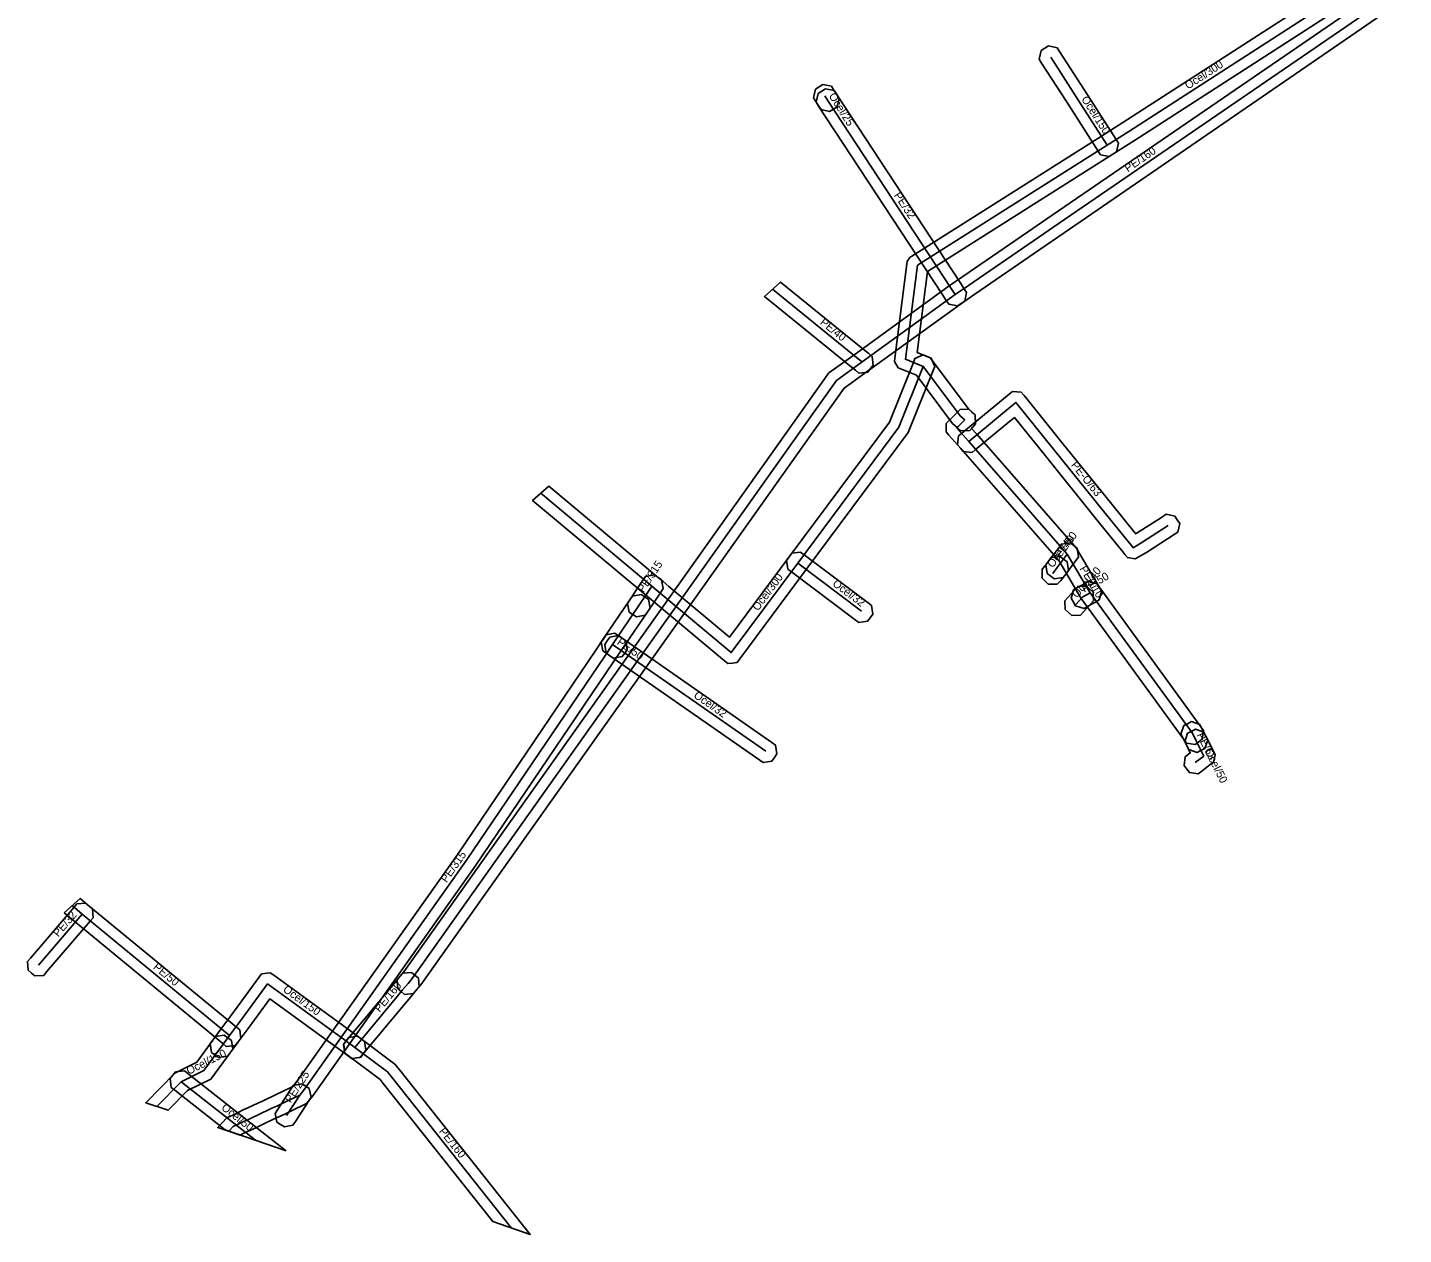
# Model space of a CAD drawing. Extents: x -492768 to -492424, y -1126490 to -1126252.
# Drawn here: x -492768.3 to -492639.3, y -1126489.8 to -1126376.7 of the extents above; entities that cross this region are included whole.
import ezdxf

# ---------------------------------------------------------------- set-up
doc = ezdxf.new("R2010")
doc.units = 0
for name, color, linetype in [('1', 7, 'Continuous'), ('14', 7, 'Continuous'), ('20', 7, 'Continuous'), ('24', 7, 'Continuous'), ('30', 7, 'Continuous')]:
    doc.layers.add(name, color=color, linetype=linetype)

msp = doc.modelspace()

# ---------------------------------------------------------------- linework, layer by layer
at = {"layer": '1'}
for points in [[(-492618.9, -1126357.81), (-492664.52, -1126387.26), (-492666.55, -1126388.54), (-492683.91, -1126399.53), (-492684.9, -1126407.12), (-492683.68, -1126407.61), (-492680.08, -1126412.41), (-492679.76, -1126412.7), (-492679.45, -1126412.97), (-492679.41, -1126413.8), (-492679.68, -1126414.11), (-492679.96, -1126414.42), (-492680.79, -1126414.46), (-492681.1, -1126414.18), (-492681.56, -1126413.77), (-492684.95, -1126409.26), (-492686.36, -1126408.69), (-492686.68, -1126408.56), (-492687.02, -1126407.97), (-492686.98, -1126407.64), (-492685.84, -1126398.81), (-492685.81, -1126398.59), (-492685.57, -1126398.21), (-492685.38, -1126398.09), (-492667.62, -1126386.85), (-492665.59, -1126385.57), (-492619.98, -1126356.13)], [(-492640.16, -1126374.66), (-492671.11, -1126395.9), (-492673.4, -1126397.47), (-492679.49, -1126401.66), (-492680.74, -1126402.52), (-492689.46, -1126408.82), (-492691.73, -1126410.46), (-492694.89, -1126414.9), (-492731.43, -1126466.4), (-492731.85, -1126466.9), (-492732.11, -1126467.21), (-492732.94, -1126467.28), (-492733.26, -1126467.01), (-492733.57, -1126466.75), (-492733.64, -1126465.92), (-492733.37, -1126465.6), (-492733.01, -1126465.18), (-492696.52, -1126413.75), (-492693.17, -1126409.03), (-492690.62, -1126407.2), (-492681.9, -1126400.88), (-492680.62, -1126400.01), (-492674.54, -1126395.83), (-492672.24, -1126394.25), (-492641.3, -1126373.02)]]:
    msp.add_lwpolyline(points, dxfattribs=at)
for points in [[(-492667.7, -1126388.59), (-492667.92, -1126388.24), (-492670.9, -1126383.6), (-492673.22, -1126379.99), (-492673.44, -1126379.64), (-492673.26, -1126378.83), (-492672.91, -1126378.61), (-492672.57, -1126378.38), (-492671.76, -1126378.56), (-492671.53, -1126378.91), (-492669.21, -1126382.53), (-492666.24, -1126387.16), (-492666.02, -1126387.51), (-492666.19, -1126388.32), (-492666.54, -1126388.54), (-492666.89, -1126388.76)], [(-492692.92, -1126382.17), (-492692.7, -1126382.52), (-492692.43, -1126382.93), (-492692.21, -1126383.28), (-492692.39, -1126384.09), (-492692.74, -1126384.31), (-492693.09, -1126384.54), (-492693.9, -1126384.36), (-492694.12, -1126384.01), (-492694.39, -1126383.6), (-492694.61, -1126383.25), (-492694.43, -1126382.44), (-492694.08, -1126382.22), (-492693.73, -1126381.99)], [(-492692.67, -1126382.57), (-492692.44, -1126382.92), (-492680.87, -1126400.57), (-492680.48, -1126401.15), (-492680.26, -1126401.5), (-492680.42, -1126402.31), (-492680.77, -1126402.54), (-492681.12, -1126402.76), (-492681.93, -1126402.59), (-492682.16, -1126402.25), (-492682.54, -1126401.66), (-492694.12, -1126384.02), (-492694.34, -1126383.67), (-492694.17, -1126382.86), (-492693.83, -1126382.63), (-492693.48, -1126382.41)], [(-492691.06, -1126408.48), (-492699.21, -1126401.86), (-492697.69, -1126400.52), (-492689.8, -1126406.92), (-492689.42, -1126407.23), (-492689.09, -1126407.49), (-492689, -1126408.31), (-492689.26, -1126408.63), (-492689.52, -1126408.96), (-492690.34, -1126409.05), (-492690.66, -1126408.79)], [(-492710.4, -1126429.79), (-492720.94, -1126420.98), (-492719.42, -1126419.65), (-492709.12, -1126428.25), (-492708.7, -1126428.6), (-492708.16, -1126429.05), (-492702.49, -1126433.79), (-492696.89, -1126426.27), (-492687.48, -1126413.64), (-492685.24, -1126408.06), (-492685.09, -1126407.68), (-492684.33, -1126407.35), (-492683.94, -1126407.5), (-492683.56, -1126407.66), (-492683.23, -1126408.42), (-492683.39, -1126408.8), (-492685.72, -1126414.62), (-492695.28, -1126427.47), (-492701.52, -1126435.84), (-492701.77, -1126436.18), (-492702.2, -1126436.23), (-492702.63, -1126436.28), (-492702.96, -1126436.01), (-492709.44, -1126430.59), (-492709.98, -1126430.14)], [(-492672.87, -1126416.81), (-492675.77, -1126413.21), (-492676.43, -1126413.76), (-492679.41, -1126416.22), (-492679.73, -1126416.49), (-492680.56, -1126416.41), (-492680.82, -1126416.09), (-492681.09, -1126415.77), (-492681.01, -1126414.94), (-492680.69, -1126414.68), (-492677.71, -1126412.22), (-492676.27, -1126411.03), (-492675.95, -1126410.77), (-492675.13, -1126410.84), (-492674.86, -1126411.16), (-492674.7, -1126411.35), (-492671.31, -1126415.55), (-492666.64, -1126421.35), (-492664.44, -1126424.06), (-492664.4, -1126424.12), (-492664.35, -1126424.09), (-492661.88, -1126422.51), (-492661.53, -1126422.28), (-492660.72, -1126422.46), (-492660.5, -1126422.81), (-492660.27, -1126423.16), (-492660.45, -1126423.97), (-492660.8, -1126424.19), (-492663.29, -1126425.79), (-492664.12, -1126426.28), (-492664.44, -1126426.47), (-492665.17, -1126426.34), (-492665.41, -1126426.05), (-492665.58, -1126425.84), (-492666, -1126425.32), (-492668.2, -1126422.61)], [(-492679.71, -1126414.13), (-492679.8, -1126414.23), (-492679.3, -1126414.79), (-492669.99, -1126425.43), (-492667.83, -1126429.09), (-492658.28, -1126442.22), (-492658.03, -1126442.55), (-492658.16, -1126443.37), (-492658.49, -1126443.61), (-492658.83, -1126443.86), (-492659.65, -1126443.73), (-492659.89, -1126443.39), (-492669.51, -1126430.19), (-492671.62, -1126426.61), (-492680.8, -1126416.11), (-492681.91, -1126414.86), (-492682.17, -1126414.57), (-492682.16, -1126413.78), (-492681.88, -1126413.5), (-492681.26, -1126412.86), (-492681.15, -1126412.75), (-492680.86, -1126412.45), (-492680.03, -1126412.43), (-492679.73, -1126412.72), (-492679.44, -1126413.01), (-492679.42, -1126413.84)], [(-492672.81, -1126427.01), (-492672.56, -1126426.68), (-492671.61, -1126425.42), (-492671.36, -1126425.09), (-492670.54, -1126424.97), (-492670.21, -1126425.22), (-492669.88, -1126425.47), (-492669.76, -1126426.29), (-492670.01, -1126426.62), (-492670.96, -1126427.89), (-492671.21, -1126428.22), (-492672.03, -1126428.33), (-492672.36, -1126428.08), (-492672.7, -1126427.83)], [(-492690.36, -1126432.42), (-492690.69, -1126432.17), (-492696.68, -1126427.67), (-492697.02, -1126427.42), (-492697.13, -1126426.6), (-492696.88, -1126426.27), (-492696.63, -1126425.94), (-492695.81, -1126425.82), (-492695.48, -1126426.07), (-492689.49, -1126430.58), (-492689.16, -1126430.82), (-492689.04, -1126431.65), (-492689.29, -1126431.98), (-492689.54, -1126432.31)], [(-492673.18, -1126427.43), (-492672.94, -1126427.19), (-492672.56, -1126426.68), (-492672.31, -1126426.35), (-492671.49, -1126426.24), (-492671.16, -1126426.49), (-492670.83, -1126426.74), (-492670.71, -1126427.56), (-492670.96, -1126427.89), (-492671.42, -1126428.5), (-492671.48, -1126428.55), (-492671.77, -1126428.84), (-492672.6, -1126428.84), (-492672.89, -1126428.55), (-492673.18, -1126428.26)], [(-492712.04, -1126430.64), (-492711.81, -1126430.29), (-492711.09, -1126429.22), (-492710.59, -1126428.47), (-492710.36, -1126428.12), (-492709.55, -1126427.96), (-492709.21, -1126428.19), (-492708.86, -1126428.42), (-492708.7, -1126429.23), (-492708.93, -1126429.58), (-492709.43, -1126430.32), (-492710.15, -1126431.41), (-492710.38, -1126431.75), (-492711.19, -1126431.91), (-492711.54, -1126431.68), (-492711.88, -1126431.45)], [(-492671.04, -1126430.39), (-492670.76, -1126430.08), (-492670.11, -1126429.36), (-492669.83, -1126429.05), (-492669.01, -1126429.01), (-492668.7, -1126429.29), (-492668.39, -1126429.57), (-492668.35, -1126430.39), (-492668.63, -1126430.7), (-492669.28, -1126431.42), (-492669.56, -1126431.73), (-492670.38, -1126431.77), (-492670.69, -1126431.49), (-492671, -1126431.21)], [(-492670.22, -1126429.36), (-492669.86, -1126429.16), (-492669.16, -1126428.77), (-492668.79, -1126428.56), (-492668, -1126428.79), (-492667.8, -1126429.15), (-492667.6, -1126429.52), (-492667.82, -1126430.31), (-492668.18, -1126430.51), (-492668.88, -1126430.9), (-492669.24, -1126431.1), (-492670.04, -1126430.88), (-492670.24, -1126430.52), (-492670.45, -1126430.16)], [(-492748.12, -1126480.36), (-492748.35, -1126480.47), (-492750.45, -1126479.75), (-492749.6, -1126478.84), (-492748.98, -1126478.56), (-492748.53, -1126478.34), (-492748.06, -1126478.12), (-492747.62, -1126477.92), (-492747.17, -1126477.7), (-492746.71, -1126477.48), (-492746.26, -1126477.28), (-492745.81, -1126477.06), (-492745.35, -1126476.84), (-492744.91, -1126476.64), (-492744.46, -1126476.42), (-492743.4, -1126475.92), (-492743.13, -1126475.58), (-492727.95, -1126454.13), (-492715.01, -1126435.01), (-492714.28, -1126433.93), (-492711.81, -1126430.29), (-492711.58, -1126429.95), (-492710.76, -1126429.79), (-492710.42, -1126430.02), (-492710.08, -1126430.26), (-492709.92, -1126431.07), (-492710.15, -1126431.41), (-492712.62, -1126435.05), (-492713.35, -1126436.13), (-492726.31, -1126455.27), (-492741.53, -1126476.78), (-492742.12, -1126477.52), (-492743.6, -1126478.22), (-492744.05, -1126478.44), (-492744.51, -1126478.66), (-492744.95, -1126478.86), (-492745.4, -1126479.08), (-492745.87, -1126479.3), (-492746.31, -1126479.5), (-492746.76, -1126479.72), (-492747.22, -1126479.94), (-492747.67, -1126480.14)], [(-492713.22, -1126433.43), (-492712.88, -1126433.67), (-492712.55, -1126433.9), (-492712.21, -1126434.14), (-492712.06, -1126434.95), (-492712.3, -1126435.29), (-492712.54, -1126435.63), (-492713.35, -1126435.78), (-492713.69, -1126435.54), (-492714.02, -1126435.31), (-492714.36, -1126435.07), (-492714.51, -1126434.26), (-492714.27, -1126433.92), (-492714.03, -1126433.58)], [(-492712.89, -1126433.66), (-492712.55, -1126433.9), (-492698.51, -1126443.68), (-492698.17, -1126443.92), (-492698.03, -1126444.74), (-492698.26, -1126445.08), (-492698.5, -1126445.42), (-492699.31, -1126445.56), (-492699.65, -1126445.32), (-492713.69, -1126435.54), (-492714.03, -1126435.3), (-492714.18, -1126434.49), (-492713.94, -1126434.15), (-492713.7, -1126433.81)], [(-492658.38, -1126441.99), (-492658.19, -1126442.36), (-492657.83, -1126443.08), (-492657.64, -1126443.45), (-492657.91, -1126444.23), (-492658.28, -1126444.42), (-492658.65, -1126444.6), (-492659.43, -1126444.34), (-492659.62, -1126443.97), (-492659.98, -1126443.25), (-492660.16, -1126442.88), (-492659.9, -1126442.09), (-492659.53, -1126441.91), (-492659.16, -1126441.72)], [(-492658.01, -1126442.71), (-492657.83, -1126443.08), (-492657.12, -1126444.5), (-492656.96, -1126444.82), (-492657.12, -1126445.52), (-492657.41, -1126445.74), (-492658.21, -1126446.35), (-492658.54, -1126446.6), (-492659.36, -1126446.49), (-492659.61, -1126446.16), (-492659.86, -1126445.82), (-492659.75, -1126445.01), (-492659.42, -1126444.75), (-492659.28, -1126444.65), (-492659.62, -1126443.97), (-492659.8, -1126443.6), (-492659.54, -1126442.81), (-492659.17, -1126442.63), (-492658.8, -1126442.44)], [(-492762.13, -1126460.11), (-492762.4, -1126460.42), (-492766.5, -1126465.18), (-492766.77, -1126465.5), (-492767.6, -1126465.56), (-492767.91, -1126465.29), (-492768.23, -1126465.02), (-492768.29, -1126464.19), (-492768.02, -1126463.88), (-492763.92, -1126459.12), (-492763.65, -1126458.8), (-492762.82, -1126458.74), (-492762.51, -1126459.01), (-492762.19, -1126459.28)], [(-492764.85, -1126459.63), (-492763.34, -1126458.29), (-492762.52, -1126459.01), (-492748.71, -1126470.36), (-492748.39, -1126470.62), (-492748.3, -1126471.45), (-492748.57, -1126471.77), (-492748.83, -1126472.08), (-492749.66, -1126472.17), (-492749.98, -1126471.9), (-492763.8, -1126460.53)], [(-492751.15, -1126471.9), (-492750.91, -1126471.57), (-492750.15, -1126470.54), (-492749.23, -1126469.29), (-492747.44, -1126466.86), (-492746.59, -1126465.71), (-492746.34, -1126465.37), (-492745.53, -1126465.25), (-492745.19, -1126465.49), (-492737.99, -1126470.74), (-492737.02, -1126471.44), (-492736.69, -1126471.69), (-492736.56, -1126472.5), (-492736.8, -1126472.84), (-492737.04, -1126473.17), (-492737.86, -1126473.3), (-492738.2, -1126473.06), (-492739.17, -1126472.35), (-492745.57, -1126467.69), (-492745.83, -1126468.05), (-492747.61, -1126470.47), (-492748.54, -1126471.72), (-492749.29, -1126472.75), (-492749.54, -1126473.09), (-492750.36, -1126473.21), (-492750.69, -1126472.97), (-492751.03, -1126472.72)], [(-492738.64, -1126471.93), (-492738.38, -1126471.61), (-492734.4, -1126466.83), (-492733.89, -1126466.22), (-492733.38, -1126465.61), (-492733.11, -1126465.29), (-492732.29, -1126465.22), (-492731.97, -1126465.48), (-492731.65, -1126465.75), (-492731.58, -1126466.57), (-492731.84, -1126466.89), (-492732.35, -1126467.5), (-492732.86, -1126468.11), (-492736.84, -1126472.89), (-492737.11, -1126473.21), (-492737.93, -1126473.28), (-492738.25, -1126473.02), (-492738.57, -1126472.75)], [(-492753.28, -1126476.3), (-492755.1, -1126478.15), (-492757.2, -1126477.44), (-492754.47, -1126474.66), (-492752.43, -1126473.64), (-492750.91, -1126471.57), (-492750.66, -1126471.24), (-492749.84, -1126471.11), (-492749.51, -1126471.35), (-492749.17, -1126471.6), (-492749.05, -1126472.42), (-492749.29, -1126472.75), (-492751.1, -1126475.22)], [(-492733.39, -1126474.4), (-492721.17, -1126489.79), (-492724.68, -1126488.58), (-492734.95, -1126475.64), (-492735.24, -1126475.27), (-492738.21, -1126473.05), (-492738.54, -1126472.8), (-492738.66, -1126471.98), (-492738.41, -1126471.65), (-492738.16, -1126471.32), (-492737.34, -1126471.2), (-492737.01, -1126471.45), (-492733.84, -1126473.83)], [(-492744.03, -1126481.95), (-492749.76, -1126479.99), (-492754.49, -1126476.26), (-492754.82, -1126476.01), (-492754.91, -1126475.18), (-492754.66, -1126474.86), (-492754.4, -1126474.53), (-492753.58, -1126474.44), (-492753.25, -1126474.69), (-492746.31, -1126480.16), (-492744.17, -1126481.84)], [(-492741.7, -1126476.92), (-492741.92, -1126477.27), (-492743.17, -1126479.19), (-492743.4, -1126479.53), (-492744.21, -1126479.7), (-492744.56, -1126479.48), (-492744.9, -1126479.25), (-492745.07, -1126478.44), (-492744.85, -1126478.09), (-492743.6, -1126476.17), (-492743.37, -1126475.83), (-492742.56, -1126475.66), (-492742.21, -1126475.88), (-492741.87, -1126476.11)]]:
    msp.add_lwpolyline(points, close=True, dxfattribs=at)
at = {"layer": '14'}
for points in [[(-492619.44, -1126356.97), (-492665.05, -1126386.42), (-492667.08, -1126387.7), (-492684.85, -1126398.94), (-492685.99, -1126407.76), (-492684.32, -1126408.43), (-492680.82, -1126413.09), (-492680.43, -1126413.44)], [(-492667.08, -1126387.7), (-492670.05, -1126383.07), (-492672.37, -1126379.45)], [(-492684.32, -1126408.43), (-492686.6, -1126414.13), (-492696.08, -1126426.87), (-492702.32, -1126435.24), (-492708.8, -1126429.82), (-492709.34, -1126429.37), (-492709.76, -1126429.02), (-492720.18, -1126420.32)], [(-492680.05, -1126415.45), (-492677.07, -1126412.99), (-492675.63, -1126411.8), (-492675.47, -1126411.99), (-492672.09, -1126416.18), (-492667.42, -1126421.98), (-492665.22, -1126424.69), (-492664.8, -1126425.21), (-492664.63, -1126425.42), (-492663.82, -1126424.94), (-492661.34, -1126423.35)], [(-492659.08, -1126442.8), (-492668.67, -1126429.64), (-492670.81, -1126426.02), (-492680.05, -1126415.45), (-492681.16, -1126414.2), (-492681.01, -1126414.04), (-492680.54, -1126413.55), (-492680.43, -1126413.44)], [(-492671.76, -1126427.28), (-492670.81, -1126426.02)], [(-492690.09, -1126431.38), (-492696.08, -1126426.87)], [(-492672.18, -1126427.84), (-492672.18, -1126427.84), (-492671.76, -1126427.28)], [(-492710.98, -1126430.85), (-492710.26, -1126429.77), (-492709.76, -1126429.02)], [(-492670.02, -1126430.75), (-492669.37, -1126430.03)], [(-492669.37, -1126430.03), (-492668.67, -1126429.64)], [(-492710.98, -1126430.85), (-492713.45, -1126434.49), (-492714.18, -1126435.57), (-492727.13, -1126454.7), (-492742.33, -1126476.18), (-492742.76, -1126476.72), (-492744.03, -1126477.32), (-492744.48, -1126477.54), (-492744.93, -1126477.75), (-492745.38, -1126477.96), (-492745.83, -1126478.18), (-492746.29, -1126478.39), (-492746.74, -1126478.6), (-492747.19, -1126478.82), (-492747.64, -1126479.03), (-492748.1, -1126479.24), (-492748.55, -1126479.46), (-492749, -1126479.67), (-492749.41, -1126480.1)], [(-492713.45, -1126434.49), (-492713.12, -1126434.72)], [(-492713.12, -1126434.72), (-492699.08, -1126444.5)], [(-492659.08, -1126442.8), (-492658.72, -1126443.52)], [(-492658.72, -1126443.52), (-492658.02, -1126444.95), (-492658.81, -1126445.55)], [(-492742.76, -1126476.72), (-492744.01, -1126478.64)]]:
    msp.add_lwpolyline(points, dxfattribs=at)
at = {"layer": '24'}
for points in [[(-492732.61, -1126466.25), (-492732.22, -1126465.79), (-492695.7, -1126414.32), (-492692.45, -1126409.74), (-492690.04, -1126408.01), (-492681.32, -1126401.7), (-492680.06, -1126400.83), (-492673.97, -1126396.65), (-492671.67, -1126395.07), (-492640.73, -1126373.84), (-492639.66, -1126373.1), (-492638.23, -1126372.04), (-492588.99, -1126335.7), (-492587.13, -1126334.33), (-492581.58, -1126330.24)], [(-492693.54, -1126383.06), (-492693.28, -1126383.47)], [(-492693.28, -1126383.47), (-492681.7, -1126401.11), (-492681.32, -1126401.7)], [(-492690.04, -1126408.01), (-492690.43, -1126407.7), (-492698.45, -1126401.19)], [(-492763.16, -1126459.77), (-492767.26, -1126464.53)], [(-492749.34, -1126471.13), (-492763.16, -1126459.77), (-492764.1, -1126458.96)], [(-492750.1, -1126472.16), (-492749.34, -1126471.13), (-492748.42, -1126469.88), (-492746.63, -1126467.46), (-492745.78, -1126466.3), (-492738.58, -1126471.54), (-492737.61, -1126472.25)], [(-492737.61, -1126472.25), (-492733.63, -1126467.47), (-492733.12, -1126466.86), (-492732.61, -1126466.25)], [(-492756.15, -1126477.79), (-492753.87, -1126475.48), (-492751.76, -1126474.43), (-492750.1, -1126472.16)], [(-492722.92, -1126489.19), (-492734.17, -1126475.02), (-492734.54, -1126474.55), (-492737.61, -1126472.25)], [(-492746.89, -1126480.97), (-492746.92, -1126480.94), (-492753.87, -1126475.48)]]:
    msp.add_lwpolyline(points, dxfattribs=at)

# ---------------------------------------------------------------- texts
at = {"layer": '20'}
for s, rotation, p in [('Ocel/300', 32.8419, (-492659.49, -1126382.49)), ('Ocel/150', 302.6796, (-492669.53, -1126383.37)), ('PE-O/63', 308.8401, (-492670.51, -1126417.69)), ('PE/50', 52.9564, (-492671.49, -1126426.45)), ('Ocel/40', 53.0147, (-492672.17, -1126427.36)), ('PE/315', 56.3099, (-492710.54, -1126429.69)), ('Ocel/300', 53.3256, (-492699.81, -1126431.4)), ('Ocel/40', 47.925, (-492669.9, -1126430.19)), ('PE/110', 300.5734, (-492669.69, -1126427.38)), ('PE/50', 29.1241, (-492669.22, -1126429.64)), ('Ocel/32', 323.0812, (-492692.89, -1126428.92)), ('PE/50', 325.1247, (-492713.09, -1126434.41)), ('Ocel/32', 325.1248, (-492705.9, -1126439.41)), ('PE/63', 296.5651, (-492658.7, -1126442.96)), ('Ocel/50', 296.5166, (-492657.95, -1126444.48)), ('PE/315', 54.7121, (-492729.01, -1126456.87)), ('PE/225', 56.9342, (-492743.61, -1126477.52))]:
    msp.add_text(s, height=0.75, rotation=rotation, dxfattribs=at).set_placement(p)
at = {"layer": '30'}
for s, rotation, p in [('Ocel/25', 302.3807, (-492693.21, -1126383.07)), ('PE/160', 34.4587, (-492665.13, -1126390.25)), ('PE/32', 303.2669, (-492687.1, -1126392.39)), ('PE/40', 320.9497, (-492694.05, -1126404.4)), ('PE/32', 49.2602, (-492765.41, -1126461.95)), ('PE/50', 320.5799, (-492756.57, -1126464.83)), ('Ocel/150', 323.9329, (-492744.4, -1126466.96)), ('PE/160', 50.218, (-492735.28, -1126469.01)), ('Ocel/150', 26.4017, (-492753.17, -1126474.83)), ('Ocel/50', 321.7998, (-492750.18, -1126478.02)), ('PE/160', 308.4466, (-492729.76, -1126480.13))]:
    msp.add_text(s, height=0.75, rotation=rotation, dxfattribs=at).set_placement(p)

doc.saveas('drawing.dxf')
